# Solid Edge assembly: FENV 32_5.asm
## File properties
Title: Zylinder
Author: bmolnar
Template: iso assembly.asm
Last saved by: bmolnar
Revision: 7
Application: Solid Edge
Username: bmolnar
Dokumentum tartalom típus: 1
Document Number: FENV 32/5
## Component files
Kolbenstange.par
Profilrohr.par
Kit_1.par
Kit_2.par
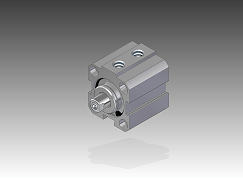
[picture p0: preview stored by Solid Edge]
